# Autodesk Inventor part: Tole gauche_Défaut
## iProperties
Shininess: 64.0
Length Units: 11269
Angle Units: 11279
Time Units: 11290
Mass Units: 11283
Length Display Precision: 3
Angle Display Precision: 2
Compacted: True
Part Number: Tole gauche_Défaut
Document SubType Name: Modeling
Created: 2006-01
Material: Par défaut
Designer: Fricot
Density: 0.0
Volumn: 0.0
Area: 0.0
PropertySet Name: Model Information
Control State: 0
Master: False
Checked Out: False
Author: Fricot
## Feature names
1. Base1
